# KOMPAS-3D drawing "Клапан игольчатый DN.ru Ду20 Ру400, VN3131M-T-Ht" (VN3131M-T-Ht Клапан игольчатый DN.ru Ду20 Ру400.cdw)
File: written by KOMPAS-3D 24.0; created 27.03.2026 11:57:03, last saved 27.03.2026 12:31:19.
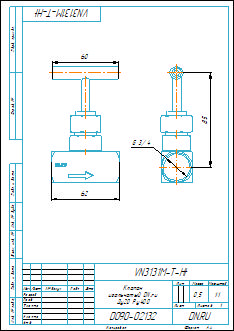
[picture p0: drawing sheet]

Document properties: Автор: Илья; Форматы листов документа: A4; Полное имя файла: VN3131M-T-Ht Клапан игольчатый DN.ru Ду20 Ру400.m3d; Масса: 0.5; Наименование: Клапан игольчатый DN.ru Ду20 Ру400; Количество листов документа: 1; Примечание: D090-02132

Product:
- Body: Body9  | qty 1
    Масса: 0.433192
- Part/product: Клапан игольчатый DN.ru Ду20 Ру400  | designation VN3131M-T-Ht
    Масса: 0.5
    Раздел спецификации: Прочие изделия
    Примечание: D090-02132

Views: Вид 1, Слева
Referenced files in D:\Обмен\Заказы с фриланса\DN.ru\VNxxM-T-Ht Клапан игольчатый DN.ru Ду8-50 Ру400\VN3232M-T-Ht Клапан игольчатый DN.ru Ду8-50 Ру400\DN8\: VN3232M-T-Ht Клапан игольчатый DN.ru Ду8 Ру400.m3d, VN3232M-T-Ht Клапан игольчатый DN.ru Ду8 Ру400.cdw
Referenced files in D:\Обмен\Заказы с фриланса\DN.ru\VNxxM-T-Ht Клапан игольчатый DN.ru Ду8-50 Ру400\VN3131M-T-Ht Клапан игольчатый DN.ru Ду8-50 Ру400\DN20\: VN3131M-T-Ht Клапан игольчатый DN.ru Ду20 Ру400.m3d
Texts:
  VN3131M-T-Ht
  Клапан
  игольчатый DN.ru
  Ду20 Ру400
  Body9
  Клапан игольчатый DN.ru Ду20 Ру400
  VN3131M-T-Ht Клапан игольчатый DN.ru Ду20 Ру400
Dimensions and other numbers on the sheet: 0; 3; 2; 4; 60; 62; 1:1; 1; 0,5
